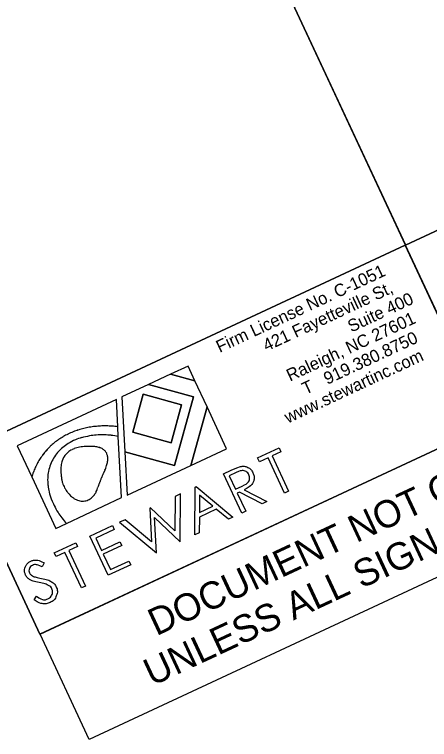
# Model space of a CAD drawing. Extents: x 2216017 to 2218023, y 761241 to 762957.
# Drawn here: x 2217434.4 to 2217518.1, y 762656.6 to 762803 of the extents above; entities that cross this region are included whole.
import ezdxf

# ---------------------------------------------------------------- set-up
doc = ezdxf.new("R2010")
doc.units = 0
for name, color, linetype in [('Sheet Plan And Profile CELL', 7, 'Continuous'), ('Sheet Sticker Exception Certification CELL', 7, 'Continuous'), ('Stewart Logo', 7, 'Continuous')]:
    doc.layers.add(name, color=color, linetype=linetype)

msp = doc.modelspace()

# ---------------------------------------------------------------- linework, layer by layer
at = {"layer": 'Sheet Plan And Profile CELL'}
msp.add_line((2217465.74, 762858.39), (2217513.27, 762756.48), dxfattribs=at)
for points in [[(2217465.74, 762858.39), (2217556.38, 762900.65), (2217603.92, 762798.69), (2217513.29, 762756.43)], [(2217375.07, 762816.11), (2217465.74, 762858.39), (2217513.29, 762756.43), (2217422.61, 762714.15)], [(2217513.29, 762756.43), (2217603.92, 762798.69), (2217620.82, 762762.44), (2217530.19, 762720.18)], [(2217422.61, 762714.15), (2217513.24, 762756.41), (2217530.15, 762720.16), (2217439.52, 762677.89)]]:
    msp.add_lwpolyline(points, close=True, dxfattribs=at)
at = {"layer": 'Sheet Sticker Exception Certification CELL'}
for p, q in [((2217439.53, 762677.9), (2217620.82, 762762.44)), ((2217630.76, 762741.14), (2217449.46, 762656.6)), ((2217449.46, 762656.6), (2217439.53, 762677.9))]:
    msp.add_line(p, q, dxfattribs=at)
at = {"layer": 'Stewart Logo'}
for p, q in [((2217469.39, 762731.99), (2217465.87, 762730.34)), ((2217470.79, 762728.99), (2217469.39, 762731.99)), ((2217465.87, 762730.34), (2217461.44, 762728.27)), ((2217465.87, 762730.34), (2217470.79, 762728.99)), ((2217470.79, 762728.99), (2217465.87, 762730.34)), ((2217473.23, 762723.76), (2217470.79, 762728.99)), ((2217461.44, 762728.27), (2217456.04, 762725.76)), ((2217461.44, 762728.27), (2217470.49, 762725.78)), ((2217470.49, 762725.78), (2217461.44, 762728.27)), ((2217470.49, 762725.78), (2217466.66, 762711.89)), ((2217466.66, 762711.89), (2217470.49, 762725.78)), ((2217454.93, 762725.24), (2217434.92, 762715.91)), ((2217455.22, 762719.74), (2217454.93, 762725.24)), ((2217456.04, 762725.76), (2217456.64, 762714.66)), ((2217465.97, 762716.49), (2217468.1, 762724.2)), ((2217473.23, 762723.76), (2217469.97, 762711.95)), ((2217469.97, 762711.95), (2217473.23, 762723.76)), ((2217477.17, 762715.31), (2217473.23, 762723.76)), ((2217447.25, 762719.09), (2217447.26, 762719.1)), ((2217452.92, 762719.91), (2217452.93, 762719.91)), ((2217455.33, 762717.79), (2217455.22, 762719.74)), ((2217447.89, 762717.51), (2217447.92, 762717.55)), ((2217456, 762705.43), (2217455.33, 762717.79)), ((2217434.92, 762715.91), (2217437.86, 762709.61)), ((2217441.61, 762715.79), (2217441.58, 762715.76)), ((2217440.82, 762714.97), (2217440.8, 762714.94)), ((2217466.66, 762711.89), (2217456.64, 762714.66)), ((2217456.64, 762714.66), (2217457.11, 762705.95)), ((2217456.64, 762714.66), (2217466.66, 762711.89)), ((2217469.97, 762711.95), (2217477.17, 762715.31)), ((2217457.11, 762705.95), (2217469.97, 762711.95)), ((2217437.86, 762709.61), (2217442.7, 762699.23)), ((2217444.85, 762700.23), (2217456, 762705.43)), ((2217466.77, 762705.68), (2217466.73, 762698.71)), ((2217467.85, 762706.18), (2217466.77, 762705.68)), ((2217467.8, 762696.51), (2217467.85, 762706.18)), ((2217461.82, 762703.37), (2217461.67, 762703.3)), ((2217461.67, 762703.3), (2217462.05, 762696.52)), ((2217466.73, 762698.71), (2217461.82, 762703.37)), ((2217456.68, 762700.98), (2217455.6, 762700.47)), ((2217462.05, 762696.52), (2217456.68, 762700.98)), ((2217463.03, 762694.28), (2217462.64, 762701.41)), ((2217462.64, 762701.41), (2217467.8, 762696.51)), ((2217442.7, 762699.23), (2217444.85, 762700.23)), ((2217455.6, 762700.47), (2217463.03, 762694.28))]:
    msp.add_line(p, q, dxfattribs=at)
msp.add_lwpolyline([(2217513.24, 762756.41), (2217422.61, 762714.15), (2217439.52, 762677.89), (2217530.15, 762720.16)], close=True, dxfattribs=at)
for points in [[(2217458.23, 762718.63), (2217460.36, 762726.34), (2217468.1, 762724.2), (2217465.97, 762716.49), (2217458.23, 762718.63)], [(2217468.1, 762724.2), (2217460.36, 762726.34), (2217458.23, 762718.63), (2217465.97, 762716.49)], [(2217449.55, 762717.91), (2217449.52, 762717.88)], [(2217440.14, 762714.14), (2217440.2, 762714.21)], [(2217483.79, 762712.67), (2217483.43, 762713.45), (2217487.77, 762715.47), (2217488.13, 762714.7), (2217486.37, 762713.87), (2217489.7, 762706.72), (2217488.89, 762706.34), (2217485.56, 762713.5), (2217483.79, 762712.67)], [(2217438.19, 762710.57), (2217438.15, 762710.5)], [(2217452.46, 762710.65), (2217452.39, 762710.51)], [(2217452.56, 762710.86), (2217452.51, 762710.77)], [(2217452.65, 762710.99), (2217452.6, 762710.92)], [(2217476.55, 762710.24), (2217478.12, 762710.97)], [(2217480.75, 762707.02), (2217485.31, 762704.67), (2217484.33, 762704.21), (2217479.76, 762706.56), (2217479.32, 762706.36), (2217481.03, 762702.68), (2217480.24, 762702.31), (2217476.55, 762710.24)], [(2217479.1, 762710.48), (2217477.7, 762709.83)], [(2217477.7, 762709.83), (2217478.96, 762707.13), (2217480.33, 762707.76)], [(2217451.33, 762707.87), (2217451.28, 762707.74)], [(2217471.02, 762707.66), (2217478.42, 762701.46), (2217477.56, 762701.06), (2217475.1, 762703.09), (2217471.68, 762701.5), (2217471.67, 762698.31), (2217470.78, 762697.9), (2217470.83, 762707.57), (2217471.02, 762707.66)], [(2217471.7, 762705.94), (2217471.69, 762702.43), (2217474.4, 762703.69), (2217471.7, 762705.94)], [(2217449.61, 762697.68), (2217454.16, 762699.8), (2217454.52, 762699.02), (2217450.77, 762697.27), (2217451.92, 762694.79), (2217455.65, 762696.52), (2217456.01, 762695.75), (2217452.29, 762694.01), (2217453.74, 762690.9), (2217457.46, 762692.63), (2217457.83, 762691.86), (2217453.31, 762689.75), (2217449.61, 762697.68)], [(2217442.77, 762693.54), (2217442.4, 762694.32), (2217446.74, 762696.34), (2217447.11, 762695.56), (2217445.34, 762694.74), (2217448.68, 762687.59), (2217447.87, 762687.21), (2217444.53, 762694.36), (2217442.77, 762693.54)], [(2217440.36, 762692.26), (2217439.94, 762691.47)], [(2217438.35, 762684.81), (2217438.83, 762685.53)]]:
    msp.add_lwpolyline(points, dxfattribs=at)
for centre, radius, start, end in [((2217451.95, 762704.38), 15.45, 111.8145, 116.0141), ((2217451.95, 762704.38), 15.45, 111.8145, 116.0141), ((2217451.95, 762704.38), 15.45, 107.6822, 111.8145), ((2217451.95, 762704.38), 15.45, 107.6822, 111.8145), ((2217452.4, 762702.96), 16.93, 103.75, 107.6822), ((2217452.4, 762702.96), 16.93, 103.75, 107.6822), ((2217452.26, 762703.53), 16.35, 99.8634, 103.75), ((2217452.26, 762703.53), 16.35, 99.8634, 103.75), ((2217452.66, 762701.23), 18.68, 96.2279, 99.8634), ((2217452.66, 762701.23), 18.68, 96.2279, 99.8634), ((2217452.53, 762702.38), 17.52, 92.6108, 96.2279), ((2217452.53, 762702.38), 17.52, 92.6108, 96.2279), ((2217452.67, 762699.31), 20.6, 89.2747, 92.6108), ((2217452.67, 762699.31), 20.6, 89.2747, 92.6108), ((2217452.67, 762700.14), 19.77, 85.9284, 89.2747), ((2217452.67, 762700.14), 19.77, 85.9284, 89.2747), ((2217452.67, 762700.14), 19.77, 82.5922, 85.9284), ((2217452.67, 762700.14), 19.77, 82.5922, 85.9284), ((2217451.32, 762705.56), 14.11, 124.7438, 129.178), ((2217451.32, 762705.56), 14.11, 124.7438, 129.178), ((2217451.43, 762705.4), 14.3, 120.339, 124.7438), ((2217451.43, 762705.4), 14.3, 120.339, 124.7438), ((2217451.57, 762705.17), 14.57, 116.0141, 120.339), ((2217451.57, 762705.17), 14.57, 116.0141, 120.339), ((2217451.39, 762706.12), 11.96, 113.2991, 120.9703), ((2217451.39, 762706.12), 11.96, 113.2991, 120.9703), ((2217450.7, 762707.72), 10.21, 105.7637, 113.2991), ((2217450.7, 762707.72), 10.21, 105.7637, 113.2991), ((2217452.18, 762702.32), 15.79, 99.7103, 105.7637), ((2217452.18, 762702.32), 15.79, 99.7103, 105.7637), ((2217451.61, 762705.9), 12.19, 93.5824, 99.7103), ((2217451.61, 762705.9), 12.19, 93.5824, 99.7103), ((2217452.09, 762698.11), 19.99, 88.7978, 93.5824), ((2217452.09, 762698.11), 19.99, 88.7978, 93.5824), ((2217452.18, 762702.32), 15.79, 83.7784, 88.7978), ((2217452.18, 762702.32), 15.79, 83.7784, 88.7978), ((2217452.01, 762700.74), 17.37, 78.9938, 83.7784), ((2217452.01, 762700.74), 17.37, 78.9938, 83.7784), ((2217451.32, 762705.56), 14.11, 133.6948, 138.1331), ((2217451.32, 762705.56), 14.11, 133.6948, 138.1331), ((2217450.95, 762706.01), 13.53, 129.178, 133.6948), ((2217450.95, 762706.01), 13.53, 129.178, 133.6948), ((2217450.06, 762708.51), 9.23, 129.9898, 139.2575), ((2217450.06, 762708.51), 9.23, 129.9898, 139.2575), ((2217449.69, 762708.95), 8.65, 120.9703, 129.9898), ((2217449.69, 762708.95), 8.65, 120.9703, 129.9898), ((2217448.72, 762709.14), 6.59, 100.6971, 105.427), ((2217448.72, 762709.14), 6.59, 100.6971, 105.427), ((2217449.07, 762707.28), 8.48, 96.5292, 100.6971), ((2217449.07, 762707.28), 8.48, 96.5292, 100.6971), ((2217449.3, 762705.26), 10.52, 92.7999, 96.5292), ((2217449.3, 762705.26), 10.52, 92.7999, 96.5292), ((2217449.2, 762707.35), 8.42, 88.632, 92.7999), ((2217449.2, 762707.35), 8.42, 88.632, 92.7999), ((2217449.72, 762709.18), 6.6, 88.9022, 92.7899), ((2217449.72, 762709.18), 6.6, 88.9022, 92.7899), ((2217449.68, 762707.11), 8.66, 85.5091, 88.9022), ((2217449.68, 762707.11), 8.66, 85.5091, 88.9022), ((2217449.84, 762709.11), 6.66, 81.6214, 85.5091), ((2217449.84, 762709.11), 6.66, 81.6214, 85.5091), ((2217450.1, 762710.88), 4.87, 77.0757, 81.6214), ((2217450.1, 762710.88), 4.87, 77.0757, 81.6214), ((2217450.23, 762711.45), 4.29, 71.8444, 77.0757), ((2217450.23, 762711.45), 4.29, 71.8444, 77.0757), ((2217450.57, 762712.49), 3.19, 65.7768, 71.8444), ((2217450.57, 762712.49), 3.19, 65.7768, 71.8444), ((2217451.54, 762705.55), 14.27, 142.649, 146.981), ((2217451.54, 762705.55), 14.27, 142.649, 146.981), ((2217450.56, 762706.19), 13.11, 138.1331, 142.649), ((2217450.56, 762706.19), 13.11, 138.1331, 142.649), ((2217449.17, 762709.27), 8.06, 139.2575, 149.1721), ((2217449.17, 762709.27), 8.06, 139.2575, 149.1721), ((2217447.51, 762711.77), 3.66, 136.8278, 144.026), ((2217447.51, 762711.77), 3.66, 136.8278, 144.026), ((2217447.59, 762711.7), 3.77, 129.7285, 136.8278), ((2217447.59, 762711.7), 3.77, 129.7285, 136.8278), ((2217447.67, 762711.6), 3.9, 122.9017, 129.7285), ((2217447.67, 762711.6), 3.9, 122.9017, 129.7285), ((2217448, 762711.1), 4.49, 116.5398, 122.9017), ((2217448, 762711.1), 4.49, 116.5398, 122.9017), ((2217448.15, 762710.79), 4.84, 110.6825, 116.5398), ((2217448.15, 762710.79), 4.84, 110.6825, 116.5398), ((2217448.56, 762709.7), 6.01, 105.427, 110.6825), ((2217448.56, 762709.7), 6.01, 105.427, 110.6825), ((2217450.72, 762712.82), 2.84, 58.8961, 65.7768), ((2217450.72, 762712.82), 2.84, 58.8961, 65.7768), ((2217451.01, 762713.31), 2.26, 51.1882, 58.8961), ((2217451.01, 762713.31), 2.26, 51.1882, 58.8961), ((2217451.12, 762713.43), 2.1, 42.8594, 51.1882), ((2217451.12, 762713.43), 2.1, 42.8594, 51.1882), ((2217451.24, 762713.55), 1.93, 34.1711, 42.8594), ((2217451.24, 762713.55), 1.93, 34.1711, 42.8594), ((2217451.24, 762713.55), 1.93, 25.507, 34.1711), ((2217451.24, 762713.55), 1.93, 25.507, 34.1711), ((2217451.06, 762713.46), 2.13, 17.2444, 25.507), ((2217451.06, 762713.46), 2.13, 17.2444, 25.507), ((2217450.9, 762713.41), 2.3, 9.6304, 17.2444), ((2217450.9, 762713.41), 2.3, 9.6304, 17.2444), ((2217450.56, 762706.19), 13.11, 146.981, 151.3831), ((2217450.56, 762706.19), 13.11, 146.981, 151.3831), ((2217449.11, 762709.31), 7.98, 149.1721, 159.1821), ((2217449.11, 762709.31), 7.98, 149.1721, 159.1821), ((2217449.01, 762711.21), 5.27, 164.1543, 169.895), ((2217449.01, 762711.21), 5.27, 164.1543, 169.895), ((2217448.14, 762711.45), 4.37, 157.8496, 164.1543), ((2217448.14, 762711.45), 4.37, 157.8496, 164.1543), ((2217447.89, 762711.56), 4.1, 151.1002, 157.8496), ((2217447.89, 762711.56), 4.1, 151.1002, 157.8496), ((2217447.57, 762711.73), 3.73, 144.026, 151.1002), ((2217447.57, 762711.73), 3.73, 144.026, 151.1002), ((2217448.2, 762713.44), 5.01, 347.2915, 351.7539), ((2217448.2, 762713.44), 5.01, 347.2915, 351.7539), ((2217450.3, 762713.31), 2.9, 2.8545, 9.6304), ((2217450.3, 762713.31), 2.9, 2.8545, 9.6304), ((2217448.8, 762713.35), 4.41, 351.7539, 356.8907), ((2217448.8, 762713.35), 4.41, 351.7539, 356.8907), ((2217449.93, 762713.29), 3.27, 356.8907, 2.8545), ((2217449.93, 762713.29), 3.27, 356.8907, 2.8545), ((2217451.21, 762705.75), 13.88, 155.5125, 159.7069), ((2217451.21, 762705.75), 13.88, 155.5125, 159.7069), ((2217452.13, 762705.33), 14.9, 151.3831, 155.5125), ((2217452.13, 762705.33), 14.9, 151.3831, 155.5125), ((2217449.89, 762709.01), 8.82, 159.1821, 168.7045), ((2217449.89, 762709.01), 8.82, 159.1821, 168.7045), ((2217451.05, 762710.99), 7.33, 175.0914, 179.7022), ((2217451.05, 762710.99), 7.33, 175.0914, 179.7022), ((2217449.5, 762711.12), 5.77, 169.895, 175.0914), ((2217449.5, 762711.12), 5.77, 169.895, 175.0914), ((2217446.43, 762713.71), 6.78, 336.3243, 340.1414), ((2217446.43, 762713.71), 6.78, 336.3243, 340.1414), ((2217444.45, 762714.43), 8.89, 340.1414, 343.4744), ((2217444.45, 762714.43), 8.89, 340.1414, 343.4744), ((2217446.41, 762713.85), 6.85, 343.4744, 347.2915), ((2217446.41, 762713.85), 6.85, 343.4744, 347.2915), ((2217451.54, 762705.55), 14.27, 159.7069, 163.485), ((2217451.54, 762705.55), 14.27, 159.7069, 163.485), ((2217449.24, 762709.14), 8.16, 168.7045, 178.1024), ((2217449.24, 762709.14), 8.16, 168.7045, 178.1024), ((2217451.81, 762710.98), 8.09, 179.7022, 183.8258), ((2217451.81, 762710.98), 8.09, 179.7022, 183.8258), ((2217454.19, 762711.14), 10.47, 183.8258, 187.4501), ((2217454.19, 762711.14), 10.47, 183.8258, 187.4501), ((2217456.65, 762711.46), 12.95, 187.4501, 190.6937), ((2217456.65, 762711.46), 12.95, 187.4501, 190.6937), ((2217485.54, 762695.75), 36.29, 157.3943, 157.7975), ((2217485.54, 762695.75), 36.29, 157.3943, 157.7975), ((2217482.54, 762697), 33.05, 156.9515, 157.3943), ((2217482.54, 762697), 33.05, 156.9515, 157.3943), ((2217477.13, 762699.3), 27.17, 156.4632, 156.9515), ((2217477.13, 762699.3), 27.17, 156.4632, 156.9515), ((2217470.75, 762702.08), 20.21, 155.8651, 156.4632), ((2217470.75, 762702.08), 20.21, 155.8651, 156.4632), ((2217466.74, 762703.88), 15.81, 155.1887, 155.8651), ((2217466.74, 762703.88), 15.81, 155.1887, 155.8651), ((2217461.04, 762706.51), 9.52, 154.2494, 155.1887), ((2217458.41, 762707.78), 6.61, 153.1219, 154.2494), ((2217458.41, 762707.78), 6.61, 153.1219, 154.2494), ((2217455.32, 762709.35), 3.14, 151.2742, 153.1219), ((2217454, 762710.07), 1.64, 148.718, 151.2741), ((2217454, 762710.07), 1.64, 148.718, 151.2741), ((2217452.81, 762710.79), 0.249, 143.0607, 148.718), ((2217453.59, 762710.21), 1.22, 140.5046, 143.0608), ((2217452.14, 762709.05), 11.07, 178.1024, 186.1689), ((2217452.14, 762709.05), 11.07, 178.1024, 186.1689), ((2217454.12, 762710.99), 10.38, 190.6937, 194.3181), ((2217454.12, 762710.99), 10.38, 190.6937, 194.3181), ((2217451.2, 762711.01), 7.59, 199.9583, 204.1125), ((2217451.2, 762711.01), 7.59, 199.9583, 204.1125), ((2217477.64, 762698.52), 27.93, 159.5909, 159.9955), ((2217477.64, 762698.52), 27.93, 159.5909, 159.9955), ((2217491.16, 762693.49), 42.35, 159.2487, 159.5909), ((2217491.16, 762693.49), 42.35, 159.2487, 159.5909), ((2217484.99, 762695.83), 35.75, 158.8764, 159.2487), ((2217484.99, 762695.83), 35.75, 158.8764, 159.2487), ((2217495.33, 762691.83), 46.84, 158.5368, 158.8764), ((2217495.33, 762691.83), 46.84, 158.5368, 158.8764), ((2217488.36, 762694.57), 39.35, 158.1663, 158.5368), ((2217488.36, 762694.57), 39.35, 158.1663, 158.5368), ((2217492.11, 762693.07), 43.39, 157.7975, 158.1663), ((2217492.11, 762693.07), 43.39, 157.7975, 158.1663), ((2217450.49, 762708.87), 9.4, 186.1689, 194.1279), ((2217450.49, 762708.87), 9.4, 186.1689, 194.1279), ((2217450.46, 762710.68), 6.78, 204.1125, 208.5072), ((2217450.46, 762710.68), 6.78, 204.1125, 208.5072), ((2217452.19, 762711.62), 8.75, 208.5072, 212.6613), ((2217452.19, 762711.62), 8.75, 208.5072, 212.6613), ((2217449.36, 762709.81), 5.39, 212.6614, 217.9555), ((2217449.36, 762709.81), 5.39, 212.6614, 217.9555), ((2217446.7, 762708.78), 4.68, 333.3257, 339.0568), ((2217446.7, 762708.78), 4.68, 333.3257, 339.0568), ((2217446.5, 762708.86), 4.9, 339.0568, 344.6622), ((2217446.5, 762708.86), 4.9, 339.0568, 344.6622), ((2217477.52, 762698.62), 27.78, 160.8419, 161.2162), ((2217477.52, 762698.62), 27.78, 160.8419, 161.2162), ((2217467.78, 762702), 17.46, 160.3698, 160.8419), ((2217482.06, 762696.91), 32.63, 159.9955, 160.3698), ((2217482.06, 762696.91), 32.63, 159.9955, 160.3698), ((2217455.48, 762710.12), 14.55, 194.1279, 200.5255), ((2217455.48, 762710.12), 14.55, 194.1279, 200.5255), ((2217450.62, 762710.79), 6.99, 217.9555, 223.184), ((2217450.62, 762710.79), 6.99, 217.9555, 223.184), ((2217448.77, 762709.05), 4.45, 223.184, 229.7361), ((2217448.77, 762709.05), 4.45, 223.184, 229.7361), ((2217449.22, 762709.58), 5.14, 229.7361, 236.5103), ((2217449.22, 762709.58), 5.14, 229.7361, 236.5103), ((2217448.33, 762708.23), 3.53, 236.5103, 244.6861), ((2217448.33, 762708.23), 3.53, 236.5103, 244.6861), ((2217448.18, 762707.43), 2.67, 303.793, 313.0103), ((2217448.18, 762707.43), 2.67, 303.793, 313.0103), ((2217447.15, 762708.53), 4.18, 313.0103, 320.379), ((2217447.15, 762708.53), 4.18, 313.0103, 320.379), ((2217447.84, 762707.95), 3.28, 320.379, 327.7203), ((2217447.84, 762707.95), 3.28, 320.379, 327.7203), ((2217445.87, 762709.2), 5.62, 327.7203, 333.3257), ((2217445.87, 762709.2), 5.62, 327.7203, 333.3257), ((2217452.39, 762708.97), 11.25, 200.5255, 206.9873), ((2217452.39, 762708.97), 11.25, 200.5255, 206.9873), ((2217458.94, 762712.3), 18.6, 206.9873, 212.0116), ((2217458.94, 762712.3), 18.6, 206.9873, 212.0116), ((2217448.37, 762708.32), 3.62, 244.6861, 253.4088), ((2217448.37, 762708.32), 3.62, 244.6861, 253.4088), ((2217448.16, 762707.61), 2.88, 253.4088, 263.184), ((2217448.16, 762707.61), 2.88, 253.4088, 263.184), ((2217448.14, 762707.44), 2.71, 263.184, 273.5685), ((2217448.14, 762707.44), 2.71, 263.184, 273.5685), ((2217448.14, 762707.46), 2.73, 273.5685, 283.9188), ((2217448.14, 762707.46), 2.73, 273.5685, 283.9188), ((2217448.21, 762707.17), 2.43, 283.9188, 294.5093), ((2217448.21, 762707.17), 2.43, 283.9188, 294.5093), ((2217447.9, 762707.83), 3.16, 294.5093, 303.793), ((2217447.9, 762707.83), 3.16, 294.5093, 303.793), ((2217455.77, 762710.32), 14.86, 212.0116, 217.2545), ((2217455.77, 762710.32), 14.86, 212.0116, 217.2545), ((2217456.82, 762711.12), 16.17, 217.2545, 222.2789), ((2217456.82, 762711.12), 16.17, 217.2545, 222.2789)]:
    msp.add_arc(centre, radius, start, end, dxfattribs=at)
for points in [[(2217478.12, 762710.97), (2217479.44, 762711.59), (2217479.96, 762711.7), (2217480.74, 762711.87), (2217481.43, 762711.54), (2217482.12, 762711.21), (2217482.48, 762710.44), (2217482.78, 762709.79), (2217482.71, 762709.15), (2217482.63, 762708.52), (2217482.19, 762708.01), (2217481.74, 762707.49), (2217480.75, 762707.02)], [(2217480.33, 762707.76), (2217481.12, 762708.13), (2217481.43, 762708.46), (2217481.74, 762708.79), (2217481.8, 762709.22), (2217481.86, 762709.65), (2217481.66, 762710.06), (2217481.48, 762710.46), (2217481.11, 762710.68), (2217480.74, 762710.91), (2217480.33, 762710.89), (2217479.91, 762710.86), (2217479.1, 762710.48)], [(2217438.83, 762685.53), (2217440.16, 762684.55), (2217441.09, 762684.99), (2217441.49, 762685.17), (2217441.75, 762685.52), (2217442.01, 762685.87), (2217442.05, 762686.27), (2217442.09, 762686.67), (2217441.93, 762687.02), (2217441.74, 762687.42), (2217441.29, 762687.67), (2217440.67, 762688.03), (2217439.34, 762688.31), (2217438, 762688.6), (2217437.6, 762688.82), (2217436.92, 762689.19), (2217436.62, 762689.84), (2217436.37, 762690.36), (2217436.42, 762690.9), (2217436.47, 762691.44), (2217436.81, 762691.89), (2217437.14, 762692.35), (2217437.67, 762692.6), (2217438.23, 762692.86), (2217438.85, 762692.81), (2217439.46, 762692.76), (2217440.36, 762692.26)], [(2217439.94, 762691.47), (2217439.21, 762691.86), (2217438.81, 762691.9), (2217438.41, 762691.94), (2217438.04, 762691.77), (2217437.56, 762691.54), (2217437.39, 762691.11), (2217437.22, 762690.68), (2217437.42, 762690.25), (2217437.54, 762689.99), (2217437.76, 762689.8), (2217437.98, 762689.61), (2217438.4, 762689.45), (2217438.62, 762689.38), (2217439.79, 762689.14), (2217441.18, 762688.86), (2217441.83, 762688.45), (2217442.49, 762688.03), (2217442.77, 762687.43), (2217443.17, 762686.57), (2217442.82, 762685.63), (2217442.46, 762684.69), (2217441.52, 762684.25), (2217440.8, 762683.92), (2217440.03, 762684.03), (2217439.27, 762684.14), (2217438.35, 762684.81)]]:
    msp.add_open_spline(points, degree=3, dxfattribs=at)

# ---------------------------------------------------------------- texts
at = {"layer": 'Sheet Sticker Exception Certification CELL'}
for s, p in [('DOCUMENT NOT CONSIDERED FINAL', (2217463, 762677.43)), ('UNLESS ALL SIGNATURES COMPLETED', (2217462.12, 762667.31))]:
    msp.add_text(s, height=5.5, rotation=25, dxfattribs=at).set_placement(p)
at = {"layer": 'Stewart Logo'}
for s, p in [('Firm License No. C-1051', (2217475.78, 762734.64)), ('421 Fayetteville St,', (2217485.23, 762734.91)), ('Suite 400', (2217502.33, 762738.74)), ('Raleigh, NC 27601', (2217489.97, 762728.84)), ('T   919.380.8750', (2217493.1, 762726.16)), ('www.stewartinc.com', (2217489.55, 762720.37))]:
    msp.add_text(s, height=2.5, rotation=25, dxfattribs=at).set_placement(p)

doc.saveas('drawing.dxf')
